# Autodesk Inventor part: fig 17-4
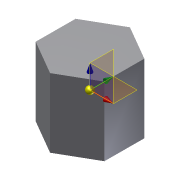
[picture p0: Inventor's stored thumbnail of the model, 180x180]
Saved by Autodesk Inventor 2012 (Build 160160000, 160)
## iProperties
Created: 2008-06
Part Number: fig 17-4
Document SubType Name: Modeling
Designer: CADCIM
Mass: 866.025 g
Surface Area: 519.615 cm^2
Volume: 866.025 cm^3
Density: 1 g/cm^3
Material: Default
Author: CADCIM
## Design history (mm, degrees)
sketch "Sketch1"
  geometry: L1 (0.184, 57.735)-(50.092, 28.708); L2 (50.092, 28.708)-(49.908, -29.027); L3 (49.908, -29.027)-(-0.184, -57.735); L4 (-0.184, -57.735)-(-50.092, -28.708); L5 (-50.092, -28.708)-(-49.908, 29.027); L6 (-49.908, 29.027)-(0.184, 57.735); 1 further point
  constraints: 12 end point, 13 other
  dimensions: "d0" = 100 distance between parallel lines of L2 L5
extrude "Extrusion1" new body sketch "Sketch1" distance "d1" = 100; taper "d2" = 0 deg
body "Solid1"
